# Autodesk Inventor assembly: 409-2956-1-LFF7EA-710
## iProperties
Created: 2010-06
Part Number: 409-2956-1-LFF7EA-710
Document SubType Name: Weldment
Designer: S. Boerckel
Mass: 43637.9 g
Surface Area: 14270.3 cm^2
Volume: 5526.84 cm^3
Density: 7.89564 g/cm^3
Description: STRAINER DISCHARGE SPOOL
Weld Material: Welded Steel Mild
Material: WELDMENT
SMR: =<MATERIAL>
Author: S. Boerckel
Revision Number: B
Subject: DEMIN WATER FORWARDING PUMP SKID-7EA
